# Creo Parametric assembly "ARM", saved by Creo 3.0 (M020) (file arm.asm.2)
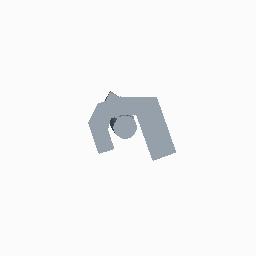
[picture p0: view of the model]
Units: millimeter Newton Second (mmNs); MM, TONNE, SECS

Created from: MMNS_ASM_DESIGN.ASM

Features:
  1. datum plane "ASM_RIGHT"
  2. datum plane "ASM_TOP"
  3. datum plane "ASM_FRONT"
  4. coordinate system
  5. component "PIPE"
  6. component "ARM_MOTOR"
  7. component "ARM_SIDE"
  8. component "ARM_SIDE"

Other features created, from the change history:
  component "ARM_MOTOR.PRT"
  component "PIPE.PRT" (2 times)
